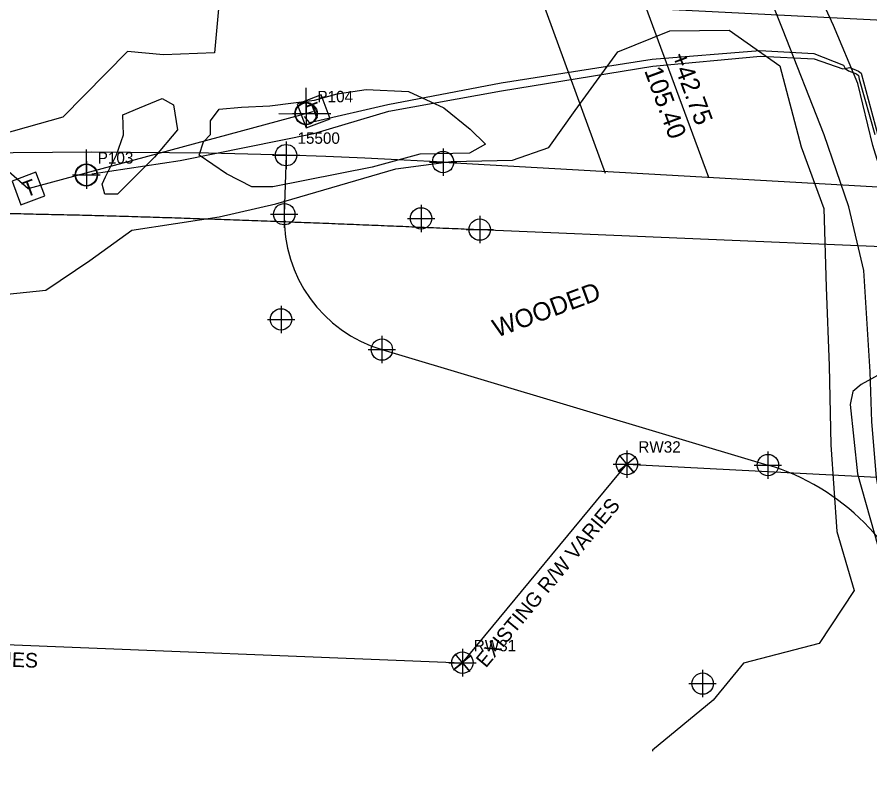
# Model space of a CAD drawing. Extents: x 2597630 to 2605918, y 617194 to 635093.
# Drawn here: x 2603848.3 to 2604035.3, y 618386.8 to 618556.4 of the extents above; entities that cross this region are included whole.
import ezdxf

# ---------------------------------------------------------------- set-up
doc = ezdxf.new("R2010")
doc.units = 0
for name, color, linetype in [('COGO Default Chain', 7, 'Continuous'), ('COGO Default Curve', 7, 'Continuous'), ('Cogo Default Point CELL', 7, 'Continuous'), ('COGO Default Point Number', 7, 'Continuous'), ('COGO Default Spiral', 7, 'Continuous'), ('Exist Property Corner CELL', 7, 'Continuous'), ('Exist Property Tie Line', 7, 'Continuous'), ('Exist Right of Way Line', 7, 'Continuous'), ('Exist Right of Way Line Text', 7, 'Continuous'), ('Exist Roads EOP', 7, 'Continuous'), ('Exist Roads Soil', 7, 'Continuous'), ('Exist Utilities Power Joint Use Telephone CELL', 7, 'Continuous'), ('Exist Utilities Power Pole CELL', 7, 'Continuous'), ('Exist Utilities Power UG Cable SUE LOS B', 7, 'Continuous'), ('Exist Utilities Telephone Pedestal CELL', 7, 'Continuous'), ('Exist Utilities Telephone UG Cable SUE LOS C', 7, 'Continuous'), ('Exist Vegetation Hedge Row', 7, 'Continuous'), ('Exist Vegetation Woods Line', 7, 'Continuous'), ('Exist Vegetation Woods Line Text', 7, 'Continuous')]:
    doc.layers.add(name, color=color, linetype=linetype)

# ---------------------------------------------------------------- blocks, each defined once
blk = doc.blocks.new('COGO DEFAULT POINT')
at = {"layer": 'Cogo Default Point CELL'}
for points in [[(0, 0.06), (0, 0)], [(-0.06, 0), (0, 0)], [(0, 0), (0.06, 0)], [(0, 0), (0, -0.06)]]:
    blk.add_lwpolyline(points, dxfattribs=at)
blk.add_circle((0, 0), 0.0469, dxfattribs=at)

msp = doc.modelspace()

# ---------------------------------------------------------------- linework, layer by layer
at = {"layer": 'COGO Default Chain'}
for p, q in [((2603907.25, 618526.11), (2603906.85, 618513.18)), ((2603941.68, 618524.59), (2605203.92, 618452.7)), ((2603949.7, 618509.81), (2604060.01, 618505.17)), ((2603949.7, 618509.81), (2605085.76, 618462.08)), ((2603949.7, 618509.81), (2605085.76, 618462.08)), ((2603928.25, 618483.51), (2604012.88, 618458.2))]:
    msp.add_line(p, q, dxfattribs=at)
for centre, radius, start, end in [((2603866.05, 617196.74), 1330, 86.74026, 110.32212), ((2603936.84, 618512.25), 30, 178.2247, 253.3541), ((2603998.56, 618410.3), 50, 16.393, 73.3541)]:
    msp.add_arc(centre, radius, start, end, dxfattribs=at)
msp.add_spline([(2603749.79, 618512.39), (2603752.49, 618512.51), (2603755.19, 618512.62), (2603757.89, 618512.73), (2603760.59, 618512.83), (2603763.29, 618512.92), (2603765.99, 618513.01), (2603768.69, 618513.09), (2603771.39, 618513.17), (2603774.1, 618513.24), (2603776.8, 618513.31), (2603779.5, 618513.37), (2603782.2, 618513.42), (2603784.91, 618513.47), (2603787.61, 618513.52), (2603790.31, 618513.56), (2603793.01, 618513.59), (2603795.71, 618513.62), (2603798.42, 618513.64), (2603801.12, 618513.66), (2603803.82, 618513.68), (2603806.53, 618513.69), (2603809.23, 618513.69), (2603811.93, 618513.69), (2603814.63, 618513.69), (2603817.34, 618513.68), (2603820.04, 618513.67), (2603822.74, 618513.65), (2603825.44, 618513.63), (2603828.15, 618513.61), (2603830.85, 618513.58), (2603833.55, 618513.55), (2603836.25, 618513.51), (2603838.96, 618513.47), (2603841.66, 618513.43), (2603844.36, 618513.38), (2603847.06, 618513.33), (2603849.77, 618513.28), (2603852.47, 618513.22), (2603855.17, 618513.16), (2603857.87, 618513.1), (2603860.57, 618513.04), (2603863.28, 618512.97), (2603865.98, 618512.9), (2603868.68, 618512.83), (2603871.38, 618512.75), (2603874.08, 618512.67), (2603876.78, 618512.59), (2603879.49, 618512.51), (2603882.19, 618512.42), (2603884.89, 618512.33), (2603887.59, 618512.24), (2603890.29, 618512.15), (2603892.99, 618512.06), (2603895.69, 618511.96), (2603898.39, 618511.87), (2603901.09, 618511.77), (2603903.8, 618511.67), (2603906.5, 618511.57), (2603909.2, 618511.46), (2603911.9, 618511.36), (2603914.6, 618511.25), (2603917.3, 618511.15), (2603920, 618511.04), (2603922.7, 618510.93), (2603925.4, 618510.82), (2603928.1, 618510.71), (2603930.8, 618510.6), (2603933.5, 618510.49), (2603936.2, 618510.37), (2603938.9, 618510.26), (2603941.6, 618510.15), (2603944.3, 618510.04), (2603947, 618509.92), (2603949.7, 618509.81)], degree=3, dxfattribs=at)
msp.add_spline([(2603749.79, 618512.39), (2603752.49, 618512.51), (2603755.19, 618512.62), (2603757.89, 618512.73), (2603760.59, 618512.83), (2603763.29, 618512.92), (2603765.99, 618513.01), (2603768.69, 618513.09), (2603771.39, 618513.17), (2603774.1, 618513.24), (2603776.8, 618513.31), (2603779.5, 618513.37), (2603782.2, 618513.42), (2603784.91, 618513.47), (2603787.61, 618513.52), (2603790.31, 618513.56), (2603793.01, 618513.59), (2603795.71, 618513.62), (2603798.42, 618513.64), (2603801.12, 618513.66), (2603803.82, 618513.68), (2603806.53, 618513.69), (2603809.23, 618513.69), (2603811.93, 618513.69), (2603814.63, 618513.69), (2603817.34, 618513.68), (2603820.04, 618513.67), (2603822.74, 618513.65), (2603825.44, 618513.63), (2603828.15, 618513.61), (2603830.85, 618513.58), (2603833.55, 618513.55), (2603836.25, 618513.51), (2603838.96, 618513.47), (2603841.66, 618513.43), (2603844.36, 618513.38), (2603847.06, 618513.33), (2603849.77, 618513.28), (2603852.47, 618513.22), (2603855.17, 618513.16), (2603857.87, 618513.1), (2603860.57, 618513.04), (2603863.28, 618512.97), (2603865.98, 618512.9), (2603868.68, 618512.83), (2603871.38, 618512.75), (2603874.08, 618512.67), (2603876.78, 618512.59), (2603879.49, 618512.51), (2603882.19, 618512.42), (2603884.89, 618512.33), (2603887.59, 618512.24), (2603890.29, 618512.15), (2603892.99, 618512.06), (2603895.69, 618511.96), (2603898.39, 618511.87), (2603901.09, 618511.77), (2603903.8, 618511.67), (2603906.5, 618511.57), (2603909.2, 618511.46), (2603911.9, 618511.36), (2603914.6, 618511.25), (2603917.3, 618511.15), (2603920, 618511.04), (2603922.7, 618510.93), (2603925.4, 618510.82), (2603928.1, 618510.71), (2603930.8, 618510.6), (2603933.5, 618510.49), (2603936.2, 618510.37), (2603938.9, 618510.26), (2603941.6, 618510.15), (2603944.3, 618510.04), (2603947, 618509.92), (2603949.7, 618509.81)], degree=3, dxfattribs=at)
msp.add_spline([(2603749.79, 618512.39), (2603752.49, 618512.51), (2603755.19, 618512.62), (2603757.89, 618512.73), (2603760.59, 618512.83), (2603763.29, 618512.92), (2603765.99, 618513.01), (2603768.69, 618513.09), (2603771.39, 618513.17), (2603774.1, 618513.24), (2603776.8, 618513.31), (2603779.5, 618513.37), (2603782.2, 618513.42), (2603784.91, 618513.47), (2603787.61, 618513.52), (2603790.31, 618513.56), (2603793.01, 618513.59), (2603795.71, 618513.62), (2603798.42, 618513.64), (2603801.12, 618513.66), (2603803.82, 618513.68), (2603806.53, 618513.69), (2603809.23, 618513.69), (2603811.93, 618513.69), (2603814.63, 618513.69), (2603817.34, 618513.68), (2603820.04, 618513.67), (2603822.74, 618513.65), (2603825.44, 618513.63), (2603828.15, 618513.61), (2603830.85, 618513.58), (2603833.55, 618513.55), (2603836.25, 618513.51), (2603838.96, 618513.47), (2603841.66, 618513.43), (2603844.36, 618513.38), (2603847.06, 618513.33), (2603849.77, 618513.28), (2603852.47, 618513.22), (2603855.17, 618513.16), (2603857.87, 618513.1), (2603860.57, 618513.04), (2603863.28, 618512.97), (2603865.98, 618512.9), (2603868.68, 618512.83), (2603871.38, 618512.75), (2603874.08, 618512.67), (2603876.78, 618512.59), (2603879.49, 618512.51), (2603882.19, 618512.42), (2603884.89, 618512.33), (2603887.59, 618512.24), (2603890.29, 618512.15), (2603892.99, 618512.06), (2603895.69, 618511.96), (2603898.39, 618511.87), (2603901.09, 618511.77), (2603903.8, 618511.67), (2603906.5, 618511.57), (2603909.2, 618511.46), (2603911.9, 618511.36), (2603914.6, 618511.25), (2603917.3, 618511.15), (2603920, 618511.04), (2603922.7, 618510.93), (2603925.4, 618510.82), (2603928.1, 618510.71), (2603930.8, 618510.6), (2603933.5, 618510.49), (2603936.2, 618510.37), (2603938.9, 618510.26), (2603941.6, 618510.15), (2603944.3, 618510.04), (2603947, 618509.92), (2603949.7, 618509.81)], degree=3, dxfattribs=at)
at = {"layer": 'COGO Default Curve'}
for centre, radius, start, end in [((2603866.05, 617196.74), 1330, 86.74026, 110.32212), ((2603936.84, 618512.25), 30, 178.2247, 253.3541), ((2603998.56, 618410.3), 50, 16.393, 73.3541)]:
    msp.add_arc(centre, radius, start, end, dxfattribs=at)
at = {"layer": 'Cogo Default Point CELL'}
for points in [[(2603941.68, 618527.59), (2603941.68, 618524.59)], [(2603938.68, 618524.59), (2603941.68, 618524.59)], [(2603941.68, 618524.59), (2603944.68, 618524.59)], [(2603941.68, 618524.59), (2603941.68, 618521.59)], [(2603906.85, 618516.18), (2603906.85, 618513.18)], [(2603936.84, 618515.25), (2603936.84, 618512.25)], [(2603903.85, 618513.18), (2603906.85, 618513.18)], [(2603906.85, 618513.18), (2603909.85, 618513.18)], [(2603906.85, 618513.18), (2603906.85, 618510.18)], [(2603933.84, 618512.25), (2603936.84, 618512.25)], [(2603936.84, 618512.25), (2603939.84, 618512.25)], [(2603936.84, 618512.25), (2603936.84, 618509.25)], [(2603949.7, 618512.81), (2603949.7, 618509.81)], [(2603946.7, 618509.81), (2603949.7, 618509.81)], [(2603949.7, 618509.81), (2603952.7, 618509.81)], [(2603949.7, 618509.81), (2603949.7, 618506.81)], [(2603906.14, 618493.12), (2603906.14, 618490.12)], [(2603903.14, 618490.12), (2603906.14, 618490.12)], [(2603906.14, 618490.12), (2603909.14, 618490.12)], [(2603906.14, 618490.12), (2603906.14, 618487.12)], [(2603928.25, 618486.51), (2603928.25, 618483.51)], [(2603925.25, 618483.51), (2603928.25, 618483.51)], [(2603928.25, 618483.51), (2603931.25, 618483.51)], [(2603928.25, 618483.51), (2603928.25, 618480.51)], [(2604012.88, 618461.2), (2604012.88, 618458.2)], [(2604009.88, 618458.2), (2604012.88, 618458.2)], [(2604012.88, 618458.2), (2604015.88, 618458.2)], [(2604012.88, 618458.2), (2604012.88, 618455.2)], [(2603998.56, 618413.3), (2603998.56, 618410.3)], [(2603995.56, 618410.3), (2603998.56, 618410.3)], [(2603998.56, 618410.3), (2604001.56, 618410.3)], [(2603998.56, 618410.3), (2603998.56, 618407.3)]]:
    msp.add_lwpolyline(points, dxfattribs=at)
for centre in [(2603941.68, 618524.59), (2603906.85, 618513.18), (2603936.84, 618512.25), (2603949.7, 618509.81), (2603906.14, 618490.12), (2603928.25, 618483.51), (2604012.88, 618458.2), (2603998.56, 618410.3)]:
    msp.add_circle(centre, 2.34, dxfattribs=at)
at = {"layer": 'COGO Default Spiral'}
msp.add_spline([(2603749.79, 618512.39), (2603752.49, 618512.51), (2603755.19, 618512.62), (2603757.89, 618512.73), (2603760.59, 618512.83), (2603763.29, 618512.92), (2603765.99, 618513.01), (2603768.69, 618513.09), (2603771.39, 618513.17), (2603774.1, 618513.24), (2603776.8, 618513.31), (2603779.5, 618513.37), (2603782.2, 618513.42), (2603784.91, 618513.47), (2603787.61, 618513.52), (2603790.31, 618513.56), (2603793.01, 618513.59), (2603795.71, 618513.62), (2603798.42, 618513.64), (2603801.12, 618513.66), (2603803.82, 618513.68), (2603806.53, 618513.69), (2603809.23, 618513.69), (2603811.93, 618513.69), (2603814.63, 618513.69), (2603817.34, 618513.68), (2603820.04, 618513.67), (2603822.74, 618513.65), (2603825.44, 618513.63), (2603828.15, 618513.61), (2603830.85, 618513.58), (2603833.55, 618513.55), (2603836.25, 618513.51), (2603838.96, 618513.47), (2603841.66, 618513.43), (2603844.36, 618513.38), (2603847.06, 618513.33), (2603849.77, 618513.28), (2603852.47, 618513.22), (2603855.17, 618513.16), (2603857.87, 618513.1), (2603860.57, 618513.04), (2603863.28, 618512.97), (2603865.98, 618512.9), (2603868.68, 618512.83), (2603871.38, 618512.75), (2603874.08, 618512.67), (2603876.78, 618512.59), (2603879.49, 618512.51), (2603882.19, 618512.42), (2603884.89, 618512.33), (2603887.59, 618512.24), (2603890.29, 618512.15), (2603892.99, 618512.06), (2603895.69, 618511.96), (2603898.39, 618511.87), (2603901.09, 618511.77), (2603903.8, 618511.67), (2603906.5, 618511.57), (2603909.2, 618511.46), (2603911.9, 618511.36), (2603914.6, 618511.25), (2603917.3, 618511.15), (2603920, 618511.04), (2603922.7, 618510.93), (2603925.4, 618510.82), (2603928.1, 618510.71), (2603930.8, 618510.6), (2603933.5, 618510.49), (2603936.2, 618510.37), (2603938.9, 618510.26), (2603941.6, 618510.15), (2603944.3, 618510.04), (2603947, 618509.92), (2603949.7, 618509.81)], degree=3, dxfattribs=at)
msp.add_spline([(2603749.79, 618512.39), (2603752.49, 618512.51), (2603755.19, 618512.62), (2603757.89, 618512.73), (2603760.59, 618512.83), (2603763.29, 618512.92), (2603765.99, 618513.01), (2603768.69, 618513.09), (2603771.39, 618513.17), (2603774.1, 618513.24), (2603776.8, 618513.31), (2603779.5, 618513.37), (2603782.2, 618513.42), (2603784.91, 618513.47), (2603787.61, 618513.52), (2603790.31, 618513.56), (2603793.01, 618513.59), (2603795.71, 618513.62), (2603798.42, 618513.64), (2603801.12, 618513.66), (2603803.82, 618513.68), (2603806.53, 618513.69), (2603809.23, 618513.69), (2603811.93, 618513.69), (2603814.63, 618513.69), (2603817.34, 618513.68), (2603820.04, 618513.67), (2603822.74, 618513.65), (2603825.44, 618513.63), (2603828.15, 618513.61), (2603830.85, 618513.58), (2603833.55, 618513.55), (2603836.25, 618513.51), (2603838.96, 618513.47), (2603841.66, 618513.43), (2603844.36, 618513.38), (2603847.06, 618513.33), (2603849.77, 618513.28), (2603852.47, 618513.22), (2603855.17, 618513.16), (2603857.87, 618513.1), (2603860.57, 618513.04), (2603863.28, 618512.97), (2603865.98, 618512.9), (2603868.68, 618512.83), (2603871.38, 618512.75), (2603874.08, 618512.67), (2603876.78, 618512.59), (2603879.49, 618512.51), (2603882.19, 618512.42), (2603884.89, 618512.33), (2603887.59, 618512.24), (2603890.29, 618512.15), (2603892.99, 618512.06), (2603895.69, 618511.96), (2603898.39, 618511.87), (2603901.09, 618511.77), (2603903.8, 618511.67), (2603906.5, 618511.57), (2603909.2, 618511.46), (2603911.9, 618511.36), (2603914.6, 618511.25), (2603917.3, 618511.15), (2603920, 618511.04), (2603922.7, 618510.93), (2603925.4, 618510.82), (2603928.1, 618510.71), (2603930.8, 618510.6), (2603933.5, 618510.49), (2603936.2, 618510.37), (2603938.9, 618510.26), (2603941.6, 618510.15), (2603944.3, 618510.04), (2603947, 618509.92), (2603949.7, 618509.81)], degree=3, dxfattribs=at)
at = {"layer": 'Exist Property Corner CELL'}
for p, q in [((2603981.98, 618458.42), (2603981.98, 618458.42)), ((2603945.9, 618414.89), (2603945.9, 618414.89))]:
    msp.add_line(p, q, dxfattribs=at)
for points in [[(2603983.9, 618460.01), (2603980.06, 618456.82), (2603981.98, 618458.42), (2603983.58, 618456.49), (2603980.38, 618460.34)], [(2603947.82, 618416.49), (2603943.98, 618413.29), (2603945.9, 618414.89), (2603947.5, 618412.97), (2603944.3, 618416.81)]]:
    msp.add_lwpolyline(points, dxfattribs=at)
at = {"layer": 'Exist Property Tie Line'}
for p, q in [((2603977.28, 618522.08), (2603923.49, 618669.11)), ((2603963.4, 618620.16), (2603999.87, 618521.28))]:
    msp.add_line(p, q, dxfattribs=at)
at = {"layer": 'Exist Right of Way Line'}
for p, q in [((2603986.18, 618558.33), (2604067.89, 618554.17)), ((2603945.9, 618414.89), (2603981.98, 618458.42)), ((2603981.98, 618458.42), (2604051.9, 618454.76)), ((2603754.05, 618422.48), (2603945.9, 618414.89))]:
    msp.add_line(p, q, dxfattribs=at)
at = {"layer": 'Exist Roads EOP'}
for points in [[(2603230.17, 618389.98), (2603282.93, 618409.6), (2603332.77, 618427.87), (2603388.17, 618448.41), (2603437.2, 618466.72), (2603490.78, 618486.53), (2603539.04, 618504.56), (2603597.45, 618526.16), (2603651.05, 618545.97), (2603705.21, 618566.08), (2603762.02, 618587.18), (2603820.33, 618609.16), (2603876.34, 618629.99), (2603934.91, 618652.28), (2603996.41, 618675.57), (2604033.22, 618689.96), (2604052.01, 618697.2)], [(2604034.63, 618668.49), (2603984.89, 618650.12), (2603936.77, 618631.65), (2603888.19, 618613.33), (2603837.77, 618594.26), (2603782.92, 618573.7), (2603731.94, 618554.39), (2603671.13, 618532.17), (2603621.82, 618514.11), (2603561.54, 618491.88), (2603506.42, 618471.29), (2603452.16, 618451.33), (2603398.36, 618431.32), (2603341.43, 618410.35), (2603281.65, 618388.2), (2603223.03, 618366.47), (2603185.72, 618352.61)]]:
    msp.add_spline(points, degree=3, dxfattribs=at)
at = {"layer": 'Exist Roads Soil'}
for points in [[(2604045.71, 618453.55), (2604044.95, 618473.57), (2604043.33, 618491.97), (2604041.8, 618507.39), (2604040.23, 618514.29), (2604035.86, 618528.23), (2604032.58, 618541.82), (2604027.28, 618554.56), (2604019.53, 618571.49), (2604012.48, 618586.03), (2604006.55, 618597.69), (2603992.13, 618636.18), (2603991.87, 618638.98), (2603991.98, 618641.65), (2603992.52, 618646.05), (2603993.33, 618649.77), (2603994.25, 618652.36), (2603995.66, 618654.1)], [(2604039.1, 618441.94), (2604036.67, 618455.51), (2604035.67, 618467.67), (2604035.28, 618478.62), (2604033.89, 618500.87), (2604030.61, 618514.78), (2604025.18, 618530.6), (2604016.09, 618553.81), (2604008.26, 618573.36), (2604002.45, 618586.83), (2603981.38, 618632.85), (2603979.81, 618635.77), (2603978.56, 618638.43), (2603977.23, 618639.27), (2603974.33, 618640.19), (2603971.15, 618640.92), (2603968.02, 618641.66), (2603964.39, 618642.32)]]:
    msp.add_lwpolyline(points, dxfattribs=at)
at = {"layer": 'Exist Utilities Power Joint Use Telephone CELL'}
msp.add_line((2603911.63, 618535.21), (2603911.63, 618535.21), dxfattribs=at)
msp.add_lwpolyline([(2603905.69, 618535.21), (2603917.03, 618535.18), (2603911.63, 618535.19), (2603911.63, 618540.84)], dxfattribs=at)
msp.add_circle((2603911.63, 618535.22), 2.45, dxfattribs=at)
at = {"layer": 'Exist Utilities Power Pole CELL'}
for q in [(2603863.46, 618527.39), (2603863.46, 618521.77)]:
    msp.add_line((2603863.46, 618521.77), q, dxfattribs=at)
msp.add_circle((2603863.46, 618521.77), 2.45, dxfattribs=at)
at = {"layer": 'Exist Utilities Power UG Cable SUE LOS B'}
for points in [[(2603911.24, 618534.59), (2603912.33, 618533.24), (2603913.73, 618533.54), (2603929.58, 618537.22), (2603954.42, 618541.94), (2603987.52, 618547.13), (2604011.14, 618549.07), (2604022.94, 618548.41), (2604029.49, 618545.83), (2604029.83, 618545.13), (2604030.54, 618544.59), (2604032.31, 618543.91), (2604032.74, 618543.56), (2604032.86, 618542.79), (2604036.3, 618530.67)], [(2603864.63, 618522.01), (2603884.05, 618524.92), (2603913.33, 618530.83), (2603929.8, 618535.76), (2603954.49, 618540.2), (2603987.67, 618545.64), (2604011.29, 618547.79), (2604023, 618547.19), (2604029.28, 618545.05), (2604030.82, 618545.32), (2604032.73, 618544.53), (2604033.33, 618544.1), (2604048.68, 618487.13), (2604051.41, 618483.75), (2604056.73, 618479.03), (2604064.83, 618477.49)], [(2604044.24, 618481.85), (2604033.36, 618475.87), (2604031.53, 618474.3), (2604030.92, 618471.45), (2604032.49, 618456.3), (2604039.86, 618430.44)]]:
    msp.add_lwpolyline(points, dxfattribs=at)
at = {"layer": 'Exist Utilities Telephone Pedestal CELL'}
for p, q in [((2603913.22, 618535.7), (2603913.22, 618535.7)), ((2603850.69, 618518.81), (2603850.69, 618518.81))]:
    msp.add_line(p, q, dxfattribs=at)
for points in [[(2603911.68, 618532.09), (2603916.91, 618534.07), (2603914.92, 618539.3), (2603909.69, 618537.32), (2603911.68, 618532.09)], [(2603849.13, 618515.2), (2603854.37, 618517.17), (2603852.41, 618522.41), (2603847.17, 618520.44), (2603849.13, 618515.2)]]:
    msp.add_lwpolyline(points, dxfattribs=at)
at = {"layer": 'Exist Utilities Telephone UG Cable SUE LOS C'}
for p, q in [((2603802.92, 618560.9), (2603850.69, 618518.81)), ((2603850.69, 618518.81), (2603913.22, 618535.7))]:
    msp.add_line(p, q, dxfattribs=at)
at = {"layer": 'Exist Vegetation Hedge Row'}
for points in [[(2603888.16, 618526.12), (2603889.11, 618529.07), (2603890.68, 618530.67), (2603890.65, 618533.61), (2603892.57, 618536.2), (2603897.46, 618536.62), (2603903.69, 618536.94), (2603913.46, 618538.15), (2603918.46, 618539.55), (2603924.8, 618540.48), (2603934.1, 618540.09), (2603941.84, 618536.51), (2603947.64, 618531.81), (2603950.98, 618528.55), (2603947.46, 618526.55), (2603936.58, 618526.31), (2603926.1, 618523.5), (2603904.38, 618519.21), (2603899.74, 618519.16), (2603894.2, 618522.03), (2603888.16, 618526.12)], [(2603871.61, 618530.58), (2603871.44, 618534.98), (2603875.09, 618536.49), (2603880.08, 618538.5), (2603882.54, 618537.18), (2603883.45, 618531.69), (2603878.39, 618525.64), (2603870.29, 618517.6), (2603867.48, 618517.57), (2603866.96, 618519.77), (2603867.68, 618521.36), (2603870.07, 618526.16), (2603871.61, 618530.58)]]:
    msp.add_lwpolyline(points, dxfattribs=at)
at = {"layer": 'Exist Vegetation Woods Line'}
for points in [[(2603839.56, 618577.55), (2603856.31, 618580.94), (2603871.88, 618590.07), (2603887.31, 618597.12), (2603905.5, 618600.37), (2603907.99, 618591.6), (2603903.65, 618580.04), (2603896.83, 618575.01), (2603892.54, 618558.97), (2603891.54, 618548.57), (2603880.35, 618548.12), (2603872.51, 618548.83), (2603858.28, 618534.44), (2603638.35, 618472.46)], [(2603836.83, 618494.7), (2603854.56, 618496.5), (2603864.24, 618503.01), (2603873.43, 618509.67), (2603892.59, 618512.6), (2603905.02, 618515.46), (2603931.32, 618523.12), (2603943.45, 618524.69), (2603956.88, 618525.01), (2603964.84, 618527.82), (2603970.66, 618535.88), (2603979.95, 618548.77), (2603991.41, 618553.38), (2604004.36, 618553.53), (2604015.48, 618545.66), (2604020.16, 618527.97), (2604025.11, 618514.43), (2604025.63, 618497.17), (2604026.3, 618479.91), (2604026.66, 618462.65), (2604027.99, 618443.64), (2604031.82, 618430.73), (2604024.12, 618419.13), (2604007.54, 618414.78), (2604000.91, 618406.71), (2603987.61, 618395.69), (2603987.58, 618395.5)]]:
    msp.add_lwpolyline(points, dxfattribs=at)

# ---------------------------------------------------------------- block references
at = {"layer": 'Cogo Default Point CELL', "xscale": 50, "yscale": 50}
for p in [(2603911.63, 618535.21), (2603907.25, 618526.11), (2603863.46, 618521.77), (2603981.98, 618458.42), (2603945.9, 618414.89)]:
    msp.add_blockref('COGO DEFAULT POINT', p, dxfattribs=at)

# ---------------------------------------------------------------- texts
at = {"layer": 'COGO Default Point Number'}
for s, p in [('P104', (2603914.13, 618537.71)), ('15500', (2603909.75, 618528.61)), ('P103', (2603865.96, 618524.27)), ('RW32', (2603984.48, 618460.92)), ('RW31', (2603948.4, 618417.39))]:
    msp.add_text(s, height=2.5, dxfattribs=at).set_placement(p)
at = {"layer": 'Exist Property Tie Line'}
for s, p in [('+42.75', (2603991.48, 618547.83)), ('105.40', (2603985.72, 618544.66))]:
    msp.add_text(s, height=4, rotation=290.2449, dxfattribs=at).set_placement(p)
at = {"layer": 'Exist Right of Way Line Text'}
for rotation, p in [(50.3433, (2603951.06, 618413.59)), (357.7351, (2603806.47, 618415.6))]:
    msp.add_text('EXISTING R/W VARIES', height=3.2, rotation=rotation, dxfattribs=at).set_placement(p)
at = {"layer": 'Exist Utilities Telephone Pedestal CELL'}
for rotation, p in [(20.7771, (2603912.77, 618533.69)), (20.5684, (2603850.23, 618516.8))]:
    msp.add_text('T', height=3.42, rotation=rotation, dxfattribs=at).set_placement(p)
at = {"layer": 'Exist Vegetation Woods Line Text'}
msp.add_text('WOODED', height=4, rotation=20.3221, dxfattribs=at).set_placement((2603953.45, 618486.1))

doc.saveas('drawing.dxf')
